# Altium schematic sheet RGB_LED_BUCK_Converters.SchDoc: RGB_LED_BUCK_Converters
size A4; Date: Not used; ApprovedBy: Not used; CheckedBy: Not used; Author: Not used; CompanyName: STMicroelectronics; DrawnBy: Not used; Engineer: Not used; Organization: Not used; Address1: Not used; Address2: Not used; Address3: Not used; Address4: Not used; DocumentNumber: Not used; Revision: Not used; SheetNumber: 6; SheetTotal: 12
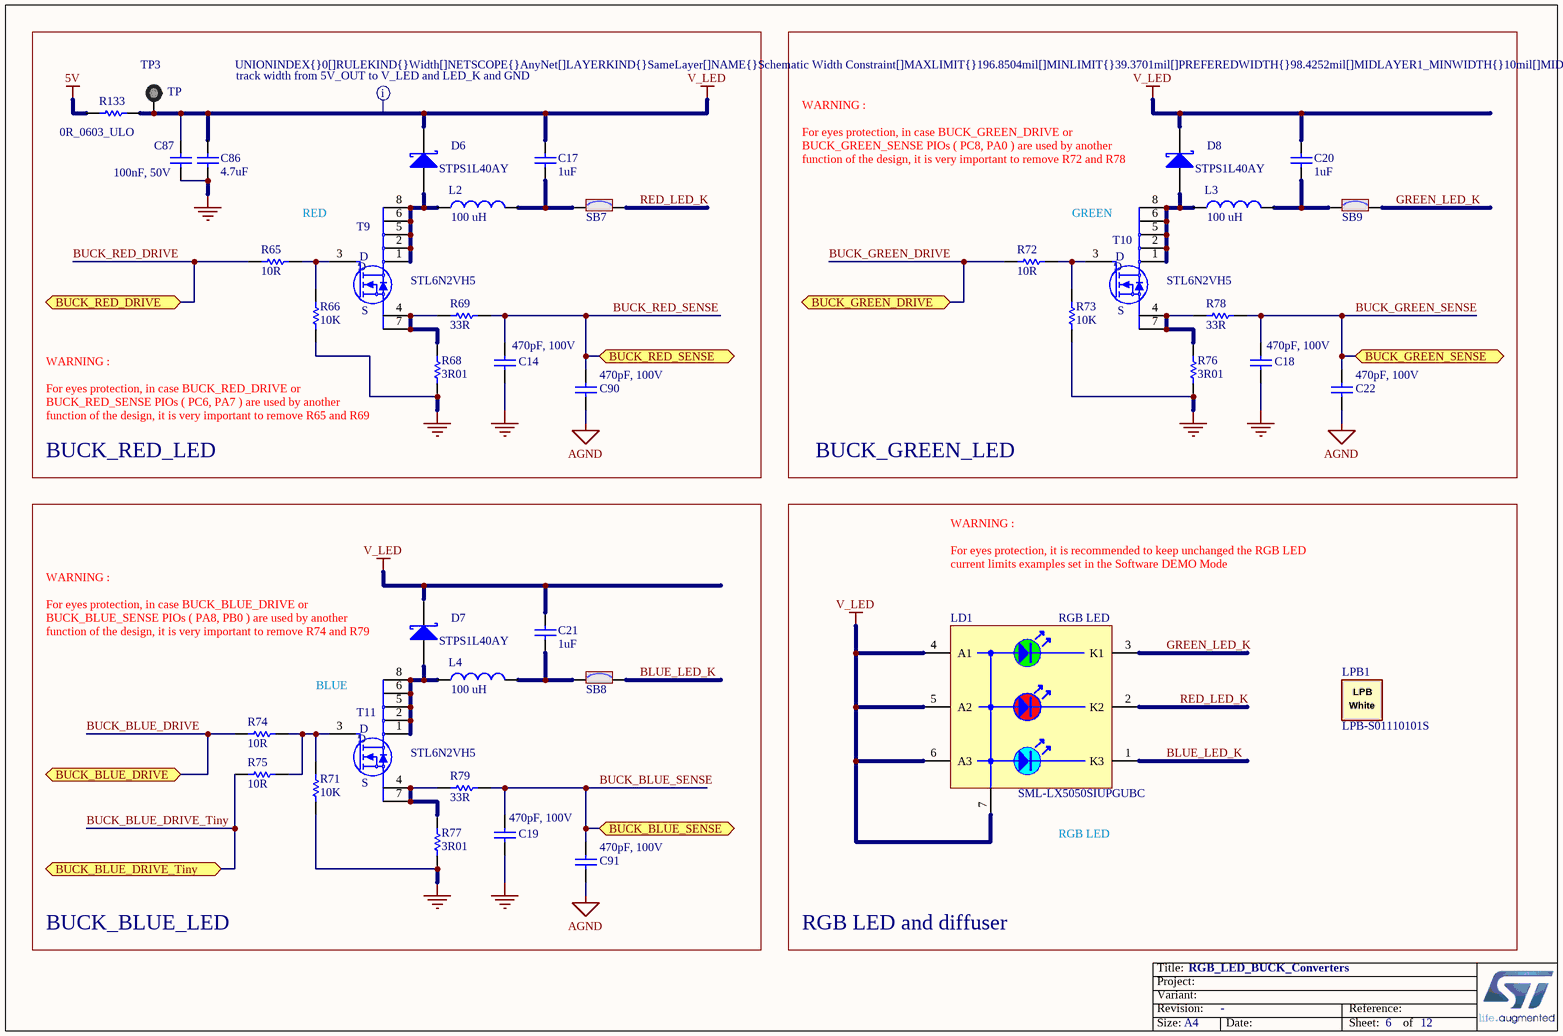
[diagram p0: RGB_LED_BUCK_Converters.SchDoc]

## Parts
C14  value 470pF, 100V  [C0603_H0P8]  (hidden comment: Capacitor)
C17  value 1uF  [C0805_H0P85]
C18  value 470pF, 100V  [C0603_H0P8]  (hidden comment: Capacitor)
C19  value 470pF, 100V  [C0603_H0P8]  (hidden comment: Capacitor)
C20  value 1uF  [C0805_H0P85]
C21  value 1uF  [C0805_H0P85]
C22  value 470pF, 100V  [C0603_H0P8]  (hidden comment: Capacitor)
C86  value 4.7uF  [C0603]
C87  value 100nF, 50V  [C0805_H0P85]
C90  value 470pF, 100V  [C0603_H0P8]  (hidden comment: Capacitor)
C91  value 470pF, 100V  [C0603_H0P8]  (hidden comment: Capacitor)
D6  value STPS1L40AY  [DIO_SMA_1A_2K]
D7  value STPS1L40AY  [DIO_SMA_1A_2K]
D8  value STPS1L40AY  [DIO_SMA_1A_2K]
L2  value 100 uH  [IND_SUNLORD_SWPA5040S]  (hidden comment: Inductor)
L3  value 100 uH  [IND_SUNLORD_SWPA5040S]  (hidden comment: Inductor)
L4  value 100 uH  [IND_SUNLORD_SWPA5040S]  (hidden comment: Inductor)
LD1  value RGB LED  Manufacturer_Part_Number: SML-LX5050SIUPGUBC  [LED_PLCC6-EPAD_LUMEX_SML-LX5050SIUPGUBC]
LPB1  LPB-S01110101S  [LIGHT_10MM-SQUARE-LIGHT-BAR_LUMEX_LPB-S01110101S]
R65  value 10R  [R0805_H0P5]
R66  value 10K  [R0805]
R68  value 3R01  [R1206_H0P55]
R69  value 33R  [R0603]
R71  value 10K  [R0805]
R72  value 10R  [R0805_H0P5]
R73  value 10K  [R0805]
R74  value 10R  [R0805_H0P5]
R75  value 10R  [R0805_H0P5]
R76  value 3R01  [R1206_H0P55]
R77  value 3R01  [R1206_H0P55]
R78  value 33R  [R0603]
R79  value 33R  [R0603]
R133  value 0R_0603_ULO  [R0603]
SB7  (no value)  [SOLDER-BRIDGE_R0603-0R]
SB8  (no value)  [SOLDER-BRIDGE_R0603-0R]
SB9  (no value)  [SOLDER-BRIDGE_R0603-0R]
T9  value STL6N2VH5  [MOS_POWERFLAT_2X2_P065]
T10  value STL6N2VH5  [MOS_POWERFLAT_2X2_P065]
T11  value STL6N2VH5  [MOS_POWERFLAT_2X2_P065]
TP3  value TP  [TP_PTH_1MM_2MM]

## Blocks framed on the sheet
BUCK_RED_LED: C14 C17 C86 C87 C90 D6 L2 R65 R66 R68 R69 R133 SB7 T9 TP3
BUCK_GREEN_LED: C18 C20 C22 D8 L3 R72 R73 R76 R78 SB9 T10
BUCK_BLUE_LED: C19 C21 C91 D7 L4 R71 R74 R75 R77 R79 SB8 T11
RGB LED and diffuser: LD1 LPB1

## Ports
BUCK_BLUE_DRIVE, BUCK_BLUE_DRIVE_Tiny, BUCK_BLUE_SENSE, BUCK_GREEN_DRIVE, BUCK_GREEN_SENSE, BUCK_RED_DRIVE, BUCK_RED_SENSE

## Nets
5V: R133.1
AGND: C22.1 C90.1 C91.1
GND: C14.1 C18.1 C19.1 C86.1 C87.1 R66.1 R68.1 R71.1 R73.1 R76.1 R77.1
V_LED: C17.2 C20.2 C21.2 C86.2 C87.2 D6.2(K) D7.2(K) D8.2(K) LD1.4(A1) LD1.5(A2) LD1.6(A3) LD1.7(SLUG) R133.2 TP3.1
BLUE_LED_K: LD1.1(K3) SB8.2
BUCK_BLUE_DRIVE: R74.1 ; port BUCK_BLUE_DRIVE
BUCK_BLUE_DRIVE_Tiny: R75.1 ; port BUCK_BLUE_DRIVE_Tiny
BUCK_BLUE_SENSE: C19.2 C91.2 R79.2 ; port BUCK_BLUE_SENSE
BUCK_GREEN_DRIVE: R72.1 ; port BUCK_GREEN_DRIVE
BUCK_GREEN_SENSE: C18.2 C22.2 R78.2 ; port BUCK_GREEN_SENSE
BUCK_RED_DRIVE: R65.1 ; port BUCK_RED_DRIVE
BUCK_RED_SENSE: C14.2 C90.2 R69.2 ; port BUCK_RED_SENSE
GREEN_LED_K: LD1.3(K1) SB9.2
RED_LED_K: LD1.2(K2) SB7.2
NetC17_1: C17.1 L2.2 SB7.1
NetC20_1: C20.1 L3.2 SB9.1
NetC21_1: C21.1 L4.2 SB8.1
NetD6_1: D6.1(A) L2.1 T9.1(D) T9.2(D) T9.5(D) T9.6(D) T9.8(D)
NetD7_1: D7.1(A) L4.1 T11.1(D) T11.2(D) T11.5(D) T11.6(D) T11.8(D)
NetD8_1: D8.1(A) L3.1 T10.1(D) T10.2(D) T10.5(D) T10.6(D) T10.8(D)
NetR65_2: R65.2 R66.2 T9.3(G)
NetR68_2: R68.2 R69.1 T9.4(S) T9.7(S)
NetR71_2: R71.2 R74.2 R75.2 T11.3(G)
NetR72_2: R72.2 R73.2 T10.3(G)
NetR76_2: R76.2 R78.1 T10.4(S) T10.7(S)
NetR77_2: R77.2 R79.1 T11.4(S) T11.7(S)

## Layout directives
rule Width Constraint [Pref Width = 2.5mm    Min Width = 1mm    Max Width = 5mm]: V_LED

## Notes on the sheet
- WARNING :
- For eyes protection, in case BUCK_GREEN_DRIVE or
- (near D8) function of the design, it is very important to remove R72 and R78
- BUCK_GREEN_SENSE PIOs ( PC8, PA0 ) are used by another
- RED
- (near T10) GREEN
- For eyes protection, in case BUCK_RED_DRIVE or
- BUCK_RED_SENSE PIOs ( PC6, PA7 ) are used by another
- (near R68) function of the design, it is very important to remove R65 and R69
- For eyes protection, it is recommended to keep unchanged the RGB LED
- current limits examples set in the Software DEMO Mode
- For eyes protection, in case BUCK_BLUE_DRIVE or
- (near D7) function of the design, it is very important to remove R74 and R79
- BUCK_BLUE_SENSE PIOs ( PA8, PB0 ) are used by another
- (near T11) BLUE
- (near LD1) RGB LED

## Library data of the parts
C14 C18 C19 C22 C90 C91 = MCD-01731: Capacitor, MLCC, 470pF, 100V, X7R, 10%, 0603, T=0.8mm; Manufacturer_Part_Number: CC0603KRX7R0BB471; Manufacturer: YAGEO; Provided_By: SUBCO
C17 C20 C21 = MCD-01550: Capacitor, MLCC, 1uF, 16V, X5R, 10%, 0805, T=0.85mm; Manufacturer_Part_Number: CC0805KRX5R7BB105; Manufacturer: YAGEO; Provided_By: SUBCO
C86 = MCD-00009: Capacitor, MLCC, 4.7uF, 16V, X5R, 10%, 0603, T=0.8mm; Manufacturer_Part_Number: CC0603KRX5R7BB475; Manufacturer: YAGEO; Provided_By: SUBCO
C87 = MCD-01525: Capacitor, MLCC, 100nF, 50V, X7R, 10%, 0805, T=0,85mm; Manufacturer_Part_Number: CC0805KRX7R9BB104; Manufacturer: YAGEO; Provided_By: SUBCO
D6-D8 = MCD-00606: Low Drop power Schottky rectifier(1A, 40V, 0.37 V); Part_Type: Diode; Manufacturer: STMICROELECTRONICS; BMS_Part_Number: 9151017; Provided_By: SUBCO with ST control
L2-L4 = MCD-01734: SMD Wire wound power inductor, 100uH, 20%, Isat 0.9A, 560mohm, 5.0x5.0x4.0mm; Manufacturer_Part_Number: SWPA5040S101MT; Manufacturer: SUNLORD; Provided_By: SUBCO
LD1 = MCD-01580: Mid Power RGB LED , SMD, 3x150 mA; Part_Type: Display; Manufacturer: LUMEX; Provided_By: SUBCO
LPB1 = MCD-01191: 10mm Square Light Bar.; Part_Type: Misc; Manufacturer: LUMEX; Alternate_Manufacturer_Part_Number: LPB-S01110101S-110945; Provided_By: SUBCO
R65 R72 R74 R75 = MCD-01548: Resistor,10R,0805,1%, 1/8W; Manufacturer_Part_Number: RC0805FR-0710RL; Manufacturer: YAGEO; Provided_By: SUBCO
R66 R71 R73 = MCD-01154: Resistor,10K,0805,1%,1/8W; Manufacturer_Part_Number: RC0805FR-0710KL; Manufacturer: YAGEO; Provided_By: SUBCO
R68 R76 R77 = MCD-01528: Resistor, 3R01, 1206, 1%, 1/4W; Manufacturer_Part_Number: RC1206FR-073R01L; Manufacturer: YAGEO; Provided_By: SUBCO
R69 R78 R79 = MCD-00456: Resistor,33R,0603,1%,1/10W; Manufacturer_Part_Number: RC0603FR-0733RL; Manufacturer: YAGEO; BMS_Part_Number: 9129732; Provided_By: SUBCO
R133 = MCD-00181: Resistor,0R,0603,ULO; Manufacturer_Part_Number: PMR03EZPJ000; Manufacturer: ROHM; Provided_By: SUBCO
SB7-SB9 = MCD-00071: Solder Bridge ON; Part_Type: Mechanical; Manufacturer_Part_Number: RC0603JR-070RL; Manufacturer: YAGEO; Provided_By: SUBCO
T9-T11 = MCD-01028: N-channel 20 V, 0.025 O typ., 6 A STripFET™ V Power MOSFET in a PowerFLAT™ 2x2 package; Part_Type: IC; Manufacturer: STMICROELECTRONICS; BMS_Part_Number: 9153558; Provided_By: SUBCO with ST control
TP3 = MCD-01506: Test Point trought hole 1mm/2mm; Part_Type: Mechanical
